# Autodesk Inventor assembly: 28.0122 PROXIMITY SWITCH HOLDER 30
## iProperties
Created: 2007-05
Part Number: 28.0122 PROXIMITY SWITCH HOLDER 30
Document SubType Name: Assembly
Designer: Andy Moles
Author: Andy Moles
